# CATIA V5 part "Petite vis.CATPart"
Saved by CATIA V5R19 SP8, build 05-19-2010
Part number: vis ski-glissière petit
Bounding box of the stored display mesh (mm): x -3.44 to 3.44, y -3.471 to 3.471, z 0 to 27
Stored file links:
  G:\EU_thinkMotion\CFAO_2010\MMS_groupe2\MMS_groupe2\A reprendre\rbouchet\rbouchet_Catia\Petite vis.CATPart
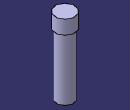
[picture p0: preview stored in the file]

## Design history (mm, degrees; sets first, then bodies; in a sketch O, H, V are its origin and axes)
Body1 (main body)
  Sketch1 on yz-plane, origin (0, 0, 0), H (0, 1, 0), V (0, 0, 1)
    line L1 (0, 27) -> (3.5, 27)
    point P1 (0, 27)
    line L2 (3.5, 27) -> (3.5, 22)
    line L3 (3.5, 22) -> (3, 22)
    line L4 (3, 22) -> (3, 0)
    line L5 (3, 0) -> (0, 0)
    point P6 (0, 0)
    length L1 = 3.5
    length L4 = 22
    length L2 = 5
    length L3 = 0.5
    distance L5 H = 0
    coincidence: P1 V, P6 V
    horizontal: L1 H, L3 H, L5 H
    vertical: L2 V, L4 V
  Shaft1: profile Sketch1, axis Sketch1.V, angle 360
